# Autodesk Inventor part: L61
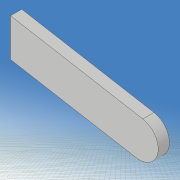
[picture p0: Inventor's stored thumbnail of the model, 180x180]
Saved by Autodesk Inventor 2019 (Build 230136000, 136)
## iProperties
Created: 2021-05
Part Number: L61
Material: 一般
Document SubType Name: Modeling
Designer: kikut
Density: 1 g/cm^3
Appearance: 既定
Mass: 0.00934248 g
Surface Area: 0.426451 cm^2
Volume: 0.00934248 cm^3
Author: kikut
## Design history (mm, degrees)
sketch "スケッチ1"
  geometry: L1 (80, 60)-(-80, 60); L2 (-80, 60)-(-80, -60); L3 (-80, -60)-(80, -60); L4 (80, -60)-(80, 60); L5 (80, 60)-(-80, -60); L6 (-80, 60)-(80, -60); 1 further point
  constraints: 12 end point, 2 midpoint, 2 parallel, 1 horizontal, 1 perpendicular
  dimensions: "d0" = 160 distance of L2.end L3.end; "d1" = 120 distance of L1.end L2.end
extrude "押し出し1" new body sketch "スケッチ1" stored distance "d2" = 0.6; taper "d3" = 0 deg
sketch "スケッチ2"
  geometry: L1 (-140, 0)-(140, 0) reference; L2 (0, -54)-(20, -30); L3 (0, 54)-(20, 30); L4 (0, -3)-(6.514, -3); L5 (6.514, -3)-(16, -6); L6 (16, -6)-(24, -3); L7 (24, -3)-(33.716, -3); L8 (0, 3)-(6.514, 3); L9 (6.514, 3)-(16, 6); L10 (16, 6)-(24, 3); L11 (24, 3)-(33.716, 3); L12 (0, -98)-(0, 98) reference; L13 (-100, -70)-(100, -70); L14 (100, -70)-(100, 70); L15 (100, 70)-(-100, 70); L16 (-100, 70)-(-100, -70); L17 (-100, -70)-(100, 70); L18 (100, -70)-(-100, 70); A1 r 60 centre (54.312, 28.5) between (0, 54) and (0, 3); A2 r 60 centre (54.312, -28.5) between (0, -3) and (0, -54); A3 r 18.111 centre (18, -12) between (20, -30) and (33.716, -3); A4 r 18.111 centre (18, 12) between (33.716, 3) and (20, 30); 1 further point
  constraints: 32 end point, 8 point on circle, 8 symmetric about line, 4 centre point, 3 horizontal, 2 collinear, 2 midpoint, 2 parallel, 1 perpendicular
  dimensions: "d5" = 60 radius of A1; "d6" = 6 distance of L8.start L4.start; "d7" = 108 distance of L3.start L2.start; "d8" = 0 horizontal distance of L3.start L8.start; "d9" = 60 distance of L3.end L2.end; "d10" = 0 horizontal distance of point (0, 0) L3.start; "d11" = 20 horizontal distance of L3.start L3.end; "d12" = 24 distance of A4.centre A3.centre; "d13" = 6 distance of L11.end L7.end; "d14" = 12 distance of L9.end L5.end; "d15" = 16 distance from line of L12 L5.end; "d16" = 24 distance from line of L6.end L12; "d17" = 200 distance of L14.end L15.end; "d18" = 140 distance of L15.end L13.start; "d30" = 18 distance from line of L12 A4.centre
extrude "押し出し2" cut sketch "スケッチ2" stored distance "d19" = 10; taper "d20" = 0 deg
sketch "スケッチ3"
  geometry: L1 (49.705, -17.97)-(33.948, -15.191); L2 (33.948, -15.191)-(34.295, -13.222); L3 (34.295, -13.222)-(50.052, -16); L4 (50.052, -16)-(49.705, -17.97); L5 (49.705, -17.97)-(34.295, -13.222); L6 (33.948, -15.191)-(50.052, -16); L7 (50.052, 16)-(34.295, 13.222); L8 (34.295, 13.222)-(33.948, 15.191); L9 (33.948, 15.191)-(49.705, 17.97); L10 (49.705, 17.97)-(50.052, 16); L11 (50.052, 16)-(33.948, 15.191); L12 (34.295, 13.222)-(49.705, 17.97); L13 (-112, 0)-(112, 0) reference; L14 (0, -84)-(0, 84) reference; 3 further points
  constraints: 24 end point, 4 midpoint, 4 parallel, 2 perpendicular, 2 symmetric about line
  dimensions: "d21" = 2 distance of L3.end L1.start; "d22" = 2 distance of L9.end L7.start; "d23" = 16 distance of L8.end L9.end; "d24" = 42 distance from line of L14 point (42, 15.596); "d26" = 10 deg angle of L7 L13; "d62" = 16 distance from line of L3.end L13
extrude "押し出し3" join sketch "スケッチ3" distance "d27" = 0.6; taper "d28" = 0 deg
fillet "フィレット1" dims "d31" = 2
fillet "フィレット2" dims "d32" = 1
sketch "スケッチ7"
  geometry: L1 (-20, 60)-(80, 60); L2 (80, 60)-(80, -60); L3 (80, -60)-(-20, -60); L4 (-20, -60)-(-20, 60); L5 (0, -82.207)-(0, 85.793) reference; L6 (-40, 0)-(100, 0) reference; L7 (42, -10)-(54, -10); L8 (54, -10)-(54, -20); L9 (54, -20)-(42, -20); L10 (42, -20)-(42, -10); 1 further point
  constraints: 16 end point, 4 parallel, 2 horizontal, 2 perpendicular, 1 other
  dimensions: "d80" = 120 distance of L3.end L1.start; "d81" = 20 distance between parallel lines of L5 L4; "d82" = 100 distance of L1.start L1.end; "d84" = 12 distance of L8.end L9.end; "d85" = 10 distance of L7.end L8.end; "d86" = 62 distance between parallel lines of L4 L10; "d93" = 40 distance between parallel lines of L3 L9
extrude "押し出し5" cut sketch "スケッチ7" stored distance "d87" = 10; taper "d88" = 0 deg
node "ソリッド1"
